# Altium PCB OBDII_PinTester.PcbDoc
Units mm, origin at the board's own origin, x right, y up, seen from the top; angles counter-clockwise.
Board outline 44 x 24 mm, 2 copper layers (Top Layer, Bottom Layer), stack 1.576 mm thick; 19 components, 19 nets, 59 pads, 6 vias.
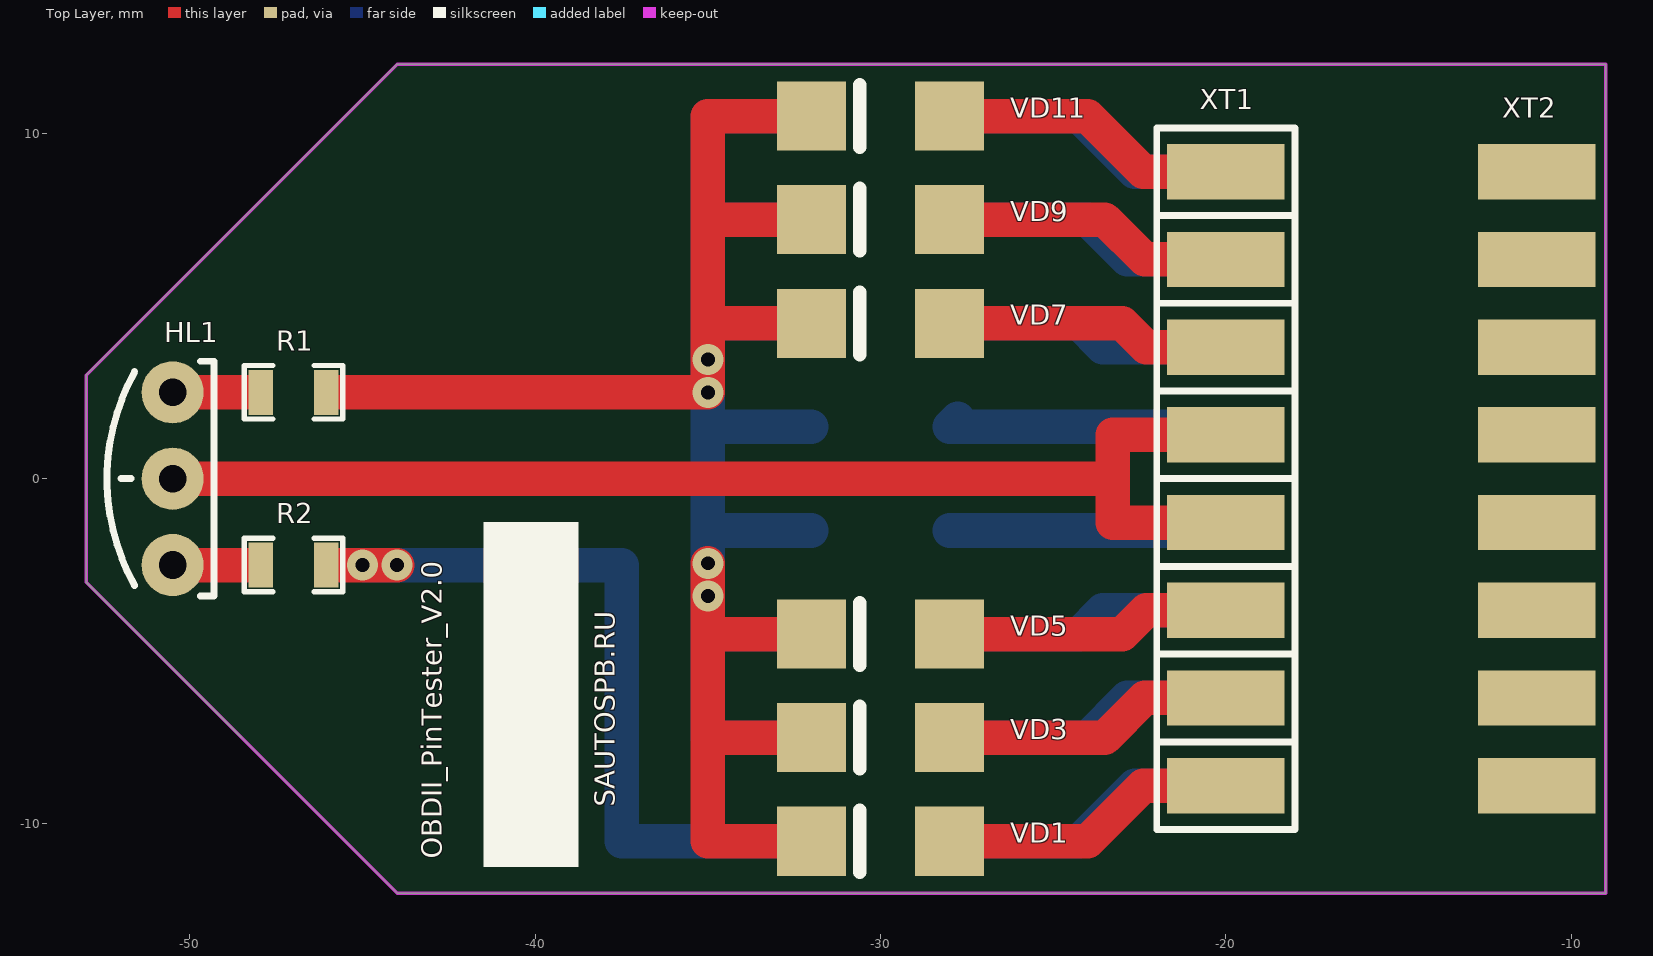
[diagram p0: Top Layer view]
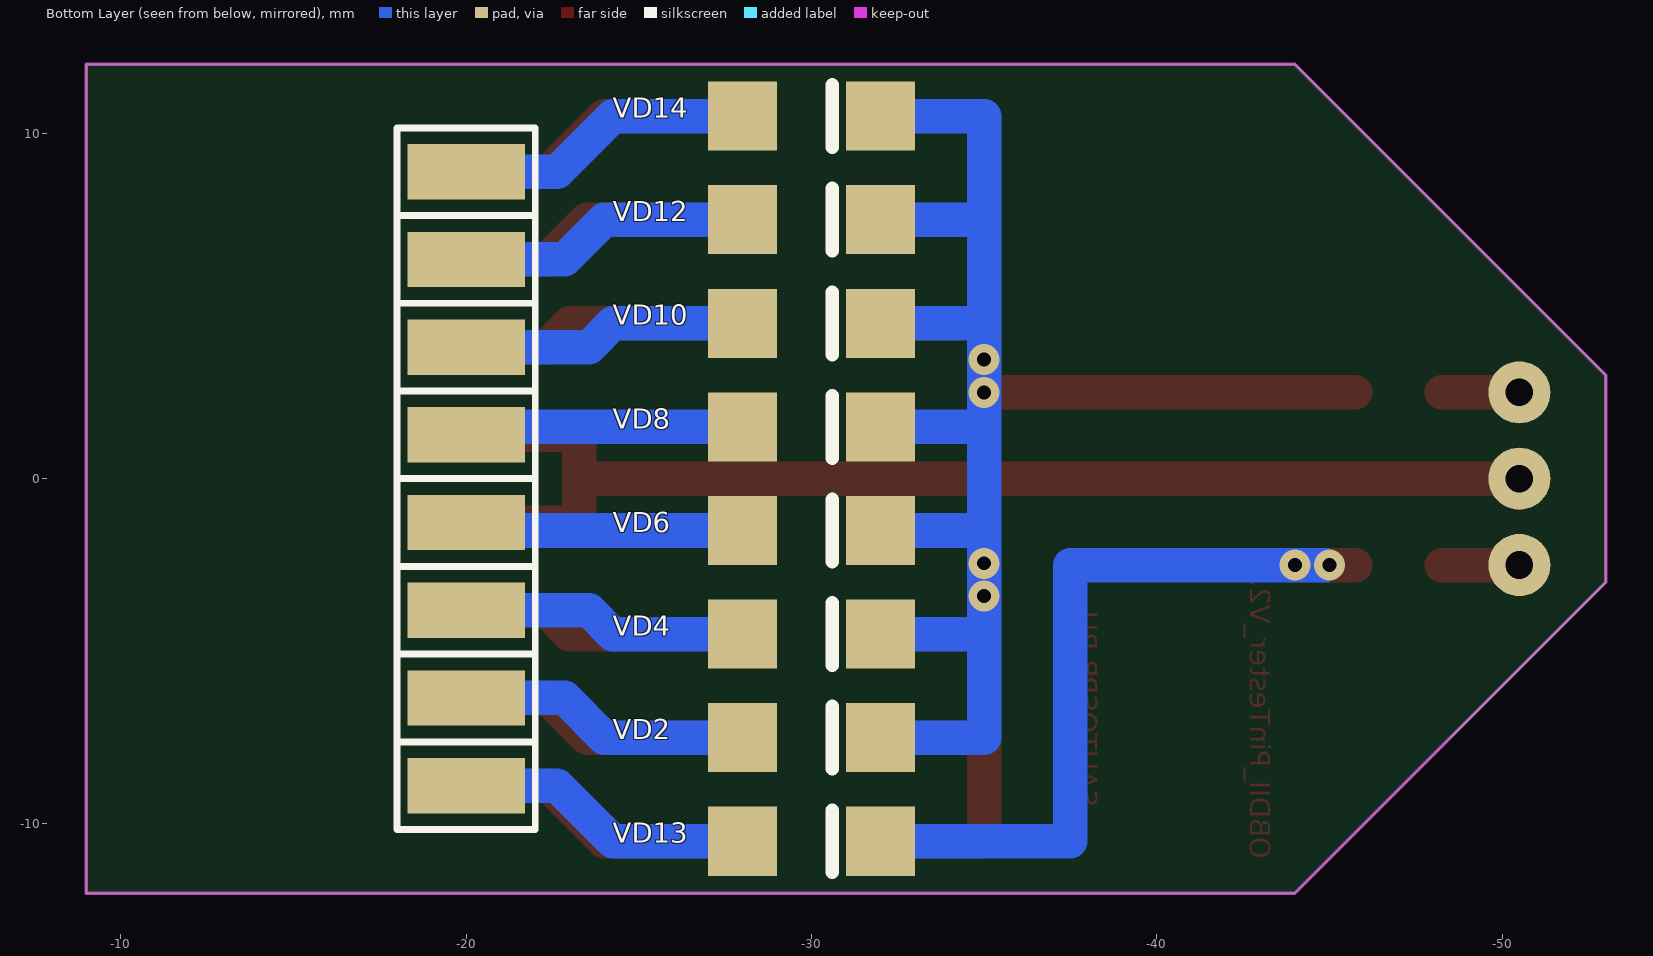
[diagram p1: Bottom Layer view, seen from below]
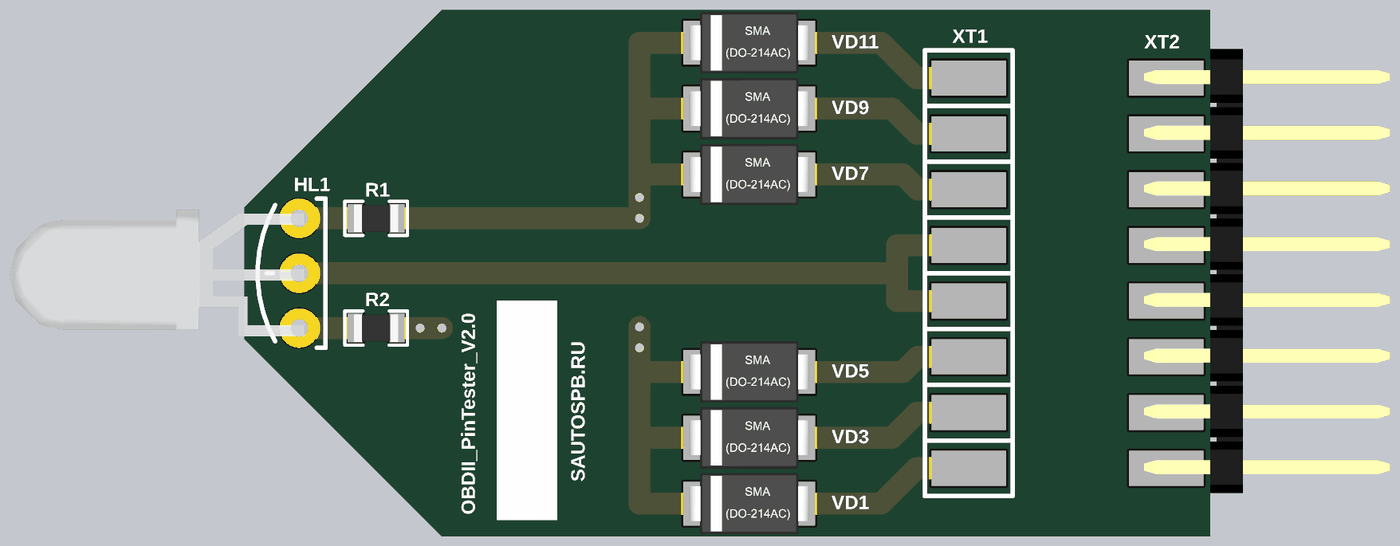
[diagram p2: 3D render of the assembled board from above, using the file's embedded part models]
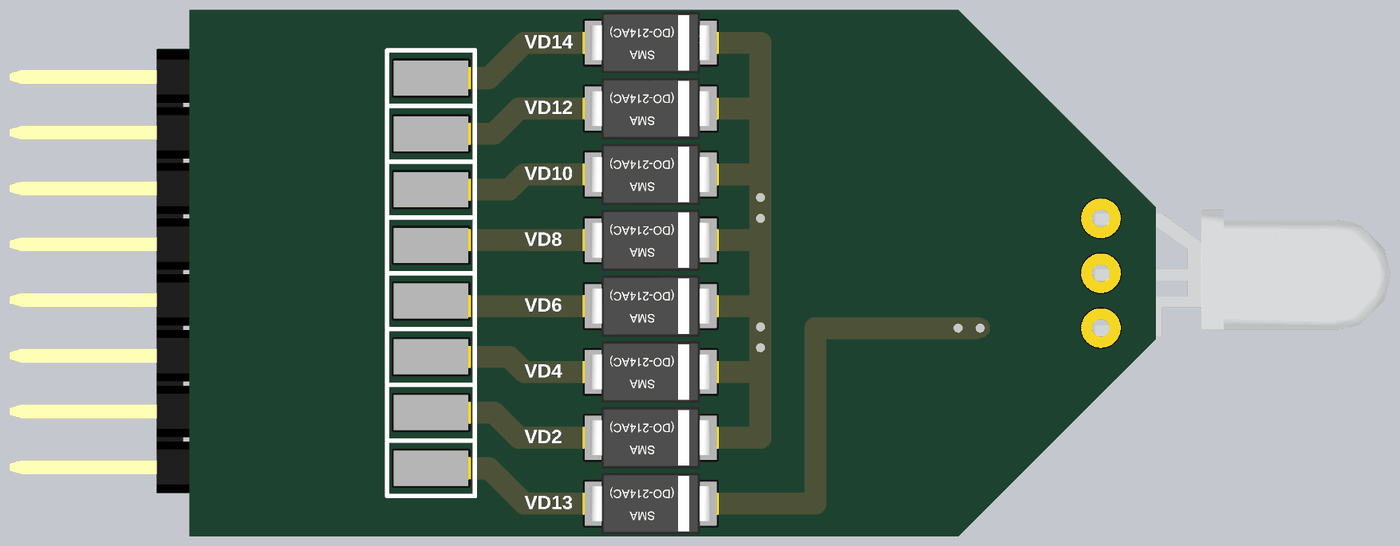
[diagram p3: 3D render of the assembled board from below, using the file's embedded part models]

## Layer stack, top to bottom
Top Solder: solder mask 0.012, Solder Resist, Dk 3.5
Top Layer: signal copper 0.018
Dielectric 1: dielectric 1.54, FR-4, Dk 4.8
Bottom Layer: signal copper 0.018
Bottom Solder: solder mask 0.012, Solder Resist, Dk 3.5

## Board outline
-53,-3 -53,3 -44,12 -9,12 -9,-12 -44,-12

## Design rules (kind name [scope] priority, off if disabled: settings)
Clearance Clearance_Poly_Inner_Keepout [InPolygon AND OnMid vs (IsTrack AND OnLayer('Keep-Out Layer')) OR HoleSize] p1: gap=0.5
Clearance Clearance_Poly_Inner [InPolygon AND OnMid] p2: gap=0.3
Clearance Clearance_Poly [InPolygon] p3: gap=0.3
Clearance [All] p4: gap=0.2
ComponentClearance [All] p1: gap=0 collisioncheckmode=3 verticalgap=0 showdistances=FALSE
Height [All] p1: minheight=0 maxheight=100 prefheight=20
HoleSize [All] p1: absolutevalues=TRUE maxlimit=10 minlimit=0.3 maxpercent=80.000 minpercent=20.000
HoleToHoleClearance [All] p1: gap=0.3 allowstackedmicrovias=TRUE
MinimumSolderMaskSliver [All] p1: minsoldermaskwidth=0
PlaneClearance [All] p1: clearance=0.5
PlaneConnect [All] p1: planeconnectstyle=Relief reliefexpansion=0.508 reliefentries=4 reliefconductorwidth=0.4 reliefairgap=0.254
PolygonConnect PolygonConnect_Via [IsVia vs IsPolygon] p1: connectstyle=Direct reliefconductorwidth=0.254 reliefentries=4 polygonreliefangle="90 Angle" airgapwidth=0.254
PolygonConnect [All] p2: connectstyle=Relief reliefconductorwidth=0.4 reliefentries=4 polygonreliefangle="90 Angle" airgapwidth=0.3
RoutingVias [All] p1: holewidth=0.4 width=0.9 viastyle="Through Hole" minholewidth=0.3 minwidth=0.7 maxholewidth=3 maxwidth=5
SilkToSilkClearance [All] p1: silktosilkclearance=0.02
SilkToSolderMaskClearance SilkscreenOverComponentPads [IsPad] p1: minsilkscreentomaskgap=0.02 clearancetoexposedcopper=TRUE
SolderMaskExpansion [All] p1: expansion=0.05
Width [All] p1: maxlimit=10 minlimit=0.2 preferedwidth=0.5
21 further rules are at their usual default settings.

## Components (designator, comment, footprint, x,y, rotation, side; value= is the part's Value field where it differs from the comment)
HL1 "LED_RG" LED_5mm_3pins_R -50.5,0 r90 top (schematic designator HL?)
R1 "10K" RES_0805 -47,2.5 r0 top
R2 "10K" RES_0805 -47,-2.5 r180 top
VD1 "*" SMA -30,-10.5 r180 top
VD2 "*" SMA -30,-7.5 r180 bottom
VD3 "*" SMA -30,-7.5 r180 top
VD4 "*" SMA -30,-4.5 r180 bottom
VD5 "*" SMA -30,-4.5 r180 top
VD6 "*" SMA -30,-1.5 r180 bottom
VD7 "*" SMA -30,4.5 r180 top
VD8 "*" SMA -30,1.5 r180 bottom
VD9 "*" SMA -30,7.5 r180 top
VD10 "*" SMA -30,4.5 r180 bottom
VD11 "*" SMA -30,10.5 r180 top
VD12 "*" SMA -30,7.5 r180 bottom
VD13 "*" SMA -30,-10.5 r180 bottom
VD14 "*" SMA -30,10.5 r180 bottom
XT1 "*" PLD-8_OBD -20,0 r90 top
XT2 "*" PLS-8_SMD -11,0 r270 top

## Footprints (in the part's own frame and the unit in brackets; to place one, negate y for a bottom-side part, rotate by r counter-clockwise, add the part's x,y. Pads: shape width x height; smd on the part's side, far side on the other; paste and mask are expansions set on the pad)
LED_5mm_3pins_R [mm]
  round 1.8 hole 0.8: 1(-2.5,0) 2(0,0) 3(2.5,0)
  silkscreen extent -3.4,-1.2 3.4,1.9, body extent -2.87,-0.25 2.87,13.19, height 3.45
PLD-8_OBD [mm] "PLD-8 Connector 2.54mm pitch"
  rect 1.6x3.4 smd mask+0.1: 1(-8.89,0) 2(-6.35,0) 3(-3.81,0) 4(-1.27,0) 5(1.27,0) 6(3.81,0) 7(6.35,0) 8(8.89,0)
  rect 1.6x3.4 smd far side mask+0.1: 9(-8.89,0) 10(-6.35,0) 11(-3.81,0) 12(-1.27,0) 13(1.27,0) 14(3.81,0) 15(6.35,0) 16(8.89,0)
PLS-8_SMD [mm] "PLS-8 Connector 2.54mm pitch"
  rect 1.6x3.4 smd mask+0.1: 1(-8.89,0) 2(-6.35,0) 3(-3.81,0) 4(-1.27,0) 5(1.27,0) 6(3.81,0) 7(6.35,0) 8(8.89,0)
  body extent -10.21,-1.01 10.01,10.19, height 1.3
RES_0805 [mm]
  rect 0.7x1.3 smd mask+0.1: 1(-0.95,0) 2(0.95,0)
  silkscreen extent -1.43,-0.78 1.43,0.78, body extent -1,-0.62 1,0.63, height 0.5
SMA [mm]
  rect 2x2 smd mask+0.1: 1(-2,0) 2(2,0)
  silkscreen extent 0.6,-0.9 0.6,0.9, body extent -2.75,-1.4 2.75,1.4, height 2.6

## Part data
HL1: "LED Red + Green Common Cathode"
R1 R2: library part RES_SMD, "Chip Resistor"
VD1 VD2 VD3 VD4 VD5 VD6 VD7 VD8 VD9 VD10 VD11 VD12 VD13 VD14: library part Diode, "Diode"
XT1: library part OBDII, "OBDII"
XT2: library part PLS-8, "Header Connector"

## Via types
v1: diameter 0.9, hole 0.4, Top Layer to Bottom Layer, tented both sides, 6 vias

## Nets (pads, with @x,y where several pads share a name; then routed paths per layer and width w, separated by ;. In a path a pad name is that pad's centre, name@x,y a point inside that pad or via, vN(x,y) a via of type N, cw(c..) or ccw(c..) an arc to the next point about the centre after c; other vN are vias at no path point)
NetHL1_1: HL1.1 R2.2 | length 2.3
  Top Layer w1: HL1.1 R2.2@-48.25,-2.5
NetHL1_2: HL1.2 XT1.4 XT1.5 | length 36.3
  Top Layer w1: HL1.2 -23.27,0 ; XT1.4 -23.27,-1.27 -23.27,0 ; XT1.5 -23.27,1.27 -23.27,0
NetHL1_3: HL1.3 R1.1 | length 2.3
  Top Layer w1: HL1.3 R1.1@-48.25,2.5
NetR1_2: R1.2 VD1.2 VD2.2 VD3.2 VD4.2 VD5.2 VD6.2 VD7.2 VD8.2 VD9.2 VD10.2 VD11.2 VD12.2 VD14.2 | length 83.8
  Top Layer w1: R1.2@-45.75,2.5 v1(-35,2.5) v1(-35,3.45) -35,4.5 ; v1(-35,-2.45) v1(-35,-3.4) -35,-4.5 ; VD1.2 -35,-10.5 -35,-7.5 ; VD3.2 -35,-7.5 ; VD5.2 -35,-4.5 ; VD7.2 -35,4.5 ; VD9.2 -35,7.5 ; VD11.2 -35,10.5 -35,7.5 ; -35,-7.5 -35,-4.5 ; -35,4.5 -35,7.5
  Bottom Layer w1: VD2.2 -35,-7.5 -35,-4.5 ; VD4.2 -35,-4.5 ; VD6.2 -35,-1.5 ; VD8.2 -35,1.5 ; VD10.2 -35,4.5 ; VD12.2 -35,7.5 ; VD14.2 -35,10.5 -35,7.5 ; -35,-4.5 v1(-35,-2.45) -35,-1.5 ; -35,-1.5 -35,1.5 ; -35,1.5 -35,4.5 ; -35,4.5 -35,7.5
NetR2_1: R2.1 VD13.2 | length 21.8
  Top Layer w1: R2.1@-45.75,-2.5 v1(-45,-2.5) v1(-44,-2.5)
  Bottom Layer w1: v1(-44,-2.5) -37.5,-2.5 -37.5,-10.5 VD13.2
NetVD1_1: VD1.1 XT1.1 | length 8.7
  Top Layer w1: VD1.1 -24,-10.5 -22.39,-8.89 XT1.1
NetVD2_1: VD2.1 XT1.10 | length 8.5
  Bottom Layer w1: VD2.1 -24,-7.5 -22.85,-6.35 XT1.10
NetVD3_1: VD3.1 XT1.2 | length 8.5
  Top Layer w1: VD3.1 -23.5,-7.5 -22.35,-6.35 XT1.2
NetVD4_1: VD4.1 XT1.11 | length 8.3
  Bottom Layer w1: VD4.1 -24.25,-4.5 -23.56,-3.81 XT1.11
NetVD5_1: VD5.1 XT1.3 | length 8.3
  Top Layer w1: VD5.1 -23,-4.5 -22.31,-3.81 XT1.3
NetVD6_1: VD6.1 XT1.12 | length 8
  Bottom Layer w1: VD6.1 XT1.12@-20,-1.5
NetVD7_1: VD7.1 XT1.6 | length 8.3
  Top Layer w1: VD7.1 -23,4.5 -22.31,3.81 XT1.6
NetVD8_1: VD8.1 XT1.13 | length 8.3
  Bottom Layer w1: VD8.1@-27.77,1.73 VD8.1 XT1.13@-20,1.5
NetVD9_1: VD9.1 XT1.7 | length 8.5
  Top Layer w1: VD9.1 -23.5,7.5 -22.35,6.35 XT1.7
NetVD10_1: VD10.1 XT1.14 | length 8.6
  Bottom Layer w1: VD10.1@-27.77,4.27 VD10.1 -24.25,4.5 -23.56,3.81 XT1.14
NetVD11_1: VD11.1 XT1.8 | length 8.7
  Top Layer w1: VD11.1 -24,10.5 -22.39,8.89 XT1.8
NetVD12_1: VD12.1 XT1.15 | length 8.5
  Bottom Layer w1: VD12.1 -24,7.5 -22.85,6.35 XT1.15
NetVD13_1: VD13.1 XT1.9 | length 8.7
  Bottom Layer w1: VD13.1 -24.25,-10.5 -22.64,-8.89 XT1.9
NetVD14_1: VD14.1 XT1.16 | length 8.7
  Bottom Layer w1: VD14.1 -24.25,10.5 -22.64,8.89 XT1.16
pads on no net: XT2.1 XT2.2 XT2.3 XT2.4 XT2.5 XT2.6 XT2.7 XT2.8

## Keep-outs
Keep-Out Layer:
  lines w0.1: -53,-3 -44,-12 -17.5,-12 -9,-12 -9,12 -17.5,12 -44,12 -53,3 -53,-3

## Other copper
Top Layer:
  region net NetR1_2: -34.6,3.45 -35.4,3.45 -35.4,2.45 -34.6,2.45
  rectangle net NetR1_2: -35.4,-3.45 -34.6,-2.45
  region net NetR2_1: -45,-2 -45,-3 -44,-3 -44,-2
  text "SAUTOSPB.RU" at -37.5,-9.5 h1 r90
  text "OBDII_PinTester_V2.0" at -42.5,-11 h1 r90
Bottom Layer:
  region net NetR1_2: -34.6,6.45 -35.4,6.45 -35.4,5.45 -34.6,5.45
  region net NetR2_1: -45,-2 -45,-3 -44,-3 -44,-2

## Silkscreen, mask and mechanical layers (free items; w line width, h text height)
Top Overlay:
  region: -41.5,-1.25 -41.5,-11.25 -38.75,-11.25 -38.75,-1.25
  lines w0.2: -22,-7.62 -18,-7.62 ; -22,-5.08 -18,-5.08 ; -22,-2.54 -18,-2.54 ; -22,0 -18,0 ; -22,2.54 -18,2.54 ; -22,5.08 -18,5.08 ; -22,7.62 -18,7.62 ; -22,-10.16 -18,-10.16 -18,10.16 -22,10.16 -22,-10.16
  text "SAUTOSPB.RU" at -37.5,-9.5 h1 r90
  text "OBDII_PinTester_V2.0" at -42.5,-11 h1 r90
Bottom Overlay:
  lines w0.2: -22,-7.62 -18,-7.62 ; -22,-5.08 -18,-5.08 ; -22,-2.54 -18,-2.54 ; -22,0 -18,0 ; -22,2.54 -18,2.54 ; -22,5.08 -18,5.08 ; -22,7.62 -18,7.62 ; -22,-10.16 -22,10.16 -18,10.16 -18,-10.16 -22,-10.16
